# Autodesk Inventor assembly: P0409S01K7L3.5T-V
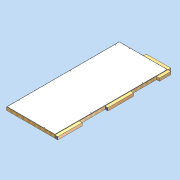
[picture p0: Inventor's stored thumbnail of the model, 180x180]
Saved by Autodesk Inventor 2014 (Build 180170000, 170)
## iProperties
Created: 2011-04
Part Number: P0409S01K7L3.5T-V
Document SubType Name: Assembly
Designer: david.appleford
Description: 1w x 2.25w  01 Panel - 7 Locks 3.5 Lugs
Mass: 49000 g
Surface Area: 73703.4 cm^2
Volume: 255168 cm^3
Density: 0.19203 g/cm^3
Cost Center: £167.00
Justset: False
Title: 1w x 2.25w  01 Panel - 7 Locks 3.5 Lugs
Author: david.appleford
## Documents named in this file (5)
- C:\Documents and Settings\john.everitt\Local Settings\My Documents\Vault\Production MkII\VIRTUAL ELEMENTS\Virtual Walls\Virtual Timber + MgO\P0409S01K7L3.5T-V.iam
- C:\Documents and Settings\john.everitt\Local Settings\My Documents\Vault\Production MkII\VIRTUAL ELEMENTS\Virtual Lugs\Superceded Lugs\LA02C3V.ipt
- C:\Documents and Settings\john.everitt\Local Settings\My Documents\Vault\Production MkII\VIRTUAL ELEMENTS\Virtual Lugs\Superceded Lugs\LA02M3V.ipt
- C:\Documents and Settings\john.everitt\Local Settings\My Documents\Vault\Production MkII\Virtual Elements\Virtual Walls\Virtual Timber + MgO\P0409S01K7-V.ipt
- C:\Documents and Settings\john.everitt\Local Settings\My Documents\Vault\Production MkII\VIRTUAL ELEMENTS\Virtual Lugs\Superceded Lugs\LA01C3V.ipt
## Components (5 placed, 4 different names)
1. P0409S01K7-V:1 — Mate:1, Flush:1, Flush:2, Mate:4, Flush:7, Flush:8, Mate:7, Flush:11, Mate:14, Flush:12, Flush:13
2. LA02C3V:1 — Mate:1, Flush:1, Flush:2, Mate:9
3. LA02C3V:3 — Mate:4, Flush:7, Flush:8
4. LA02M3V:4 — Mate:7, Flush:11, Mate:9
5. LA01C3V:1 — Mate:14, Flush:12, Flush:13
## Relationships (12: Flush 7, Mate 5)
- Mate:1: P0409S01K7-V:1 ↔ LA02C3V:1
- Flush:1: P0409S01K7-V:1 ↔ LA02C3V:1
- Flush:2: P0409S01K7-V:1 ↔ LA02C3V:1
- Mate:4: P0409S01K7-V:1 ↔ LA02C3V:3
- Flush:7: P0409S01K7-V:1 ↔ LA02C3V:3
- Flush:8: P0409S01K7-V:1 ↔ LA02C3V:3
- Mate:7: P0409S01K7-V:1 ↔ LA02M3V:4
- Flush:11: P0409S01K7-V:1 ↔ LA02M3V:4
- Mate:9: LA02C3V:1 ↔ LA02M3V:4
- Mate:14: P0409S01K7-V:1 ↔ LA01C3V:1
- Flush:12: P0409S01K7-V:1 ↔ LA01C3V:1
- Flush:13: P0409S01K7-V:1 ↔ LA01C3V:1
## Named parameters: t = 1 mm, Cl = 2 mm
